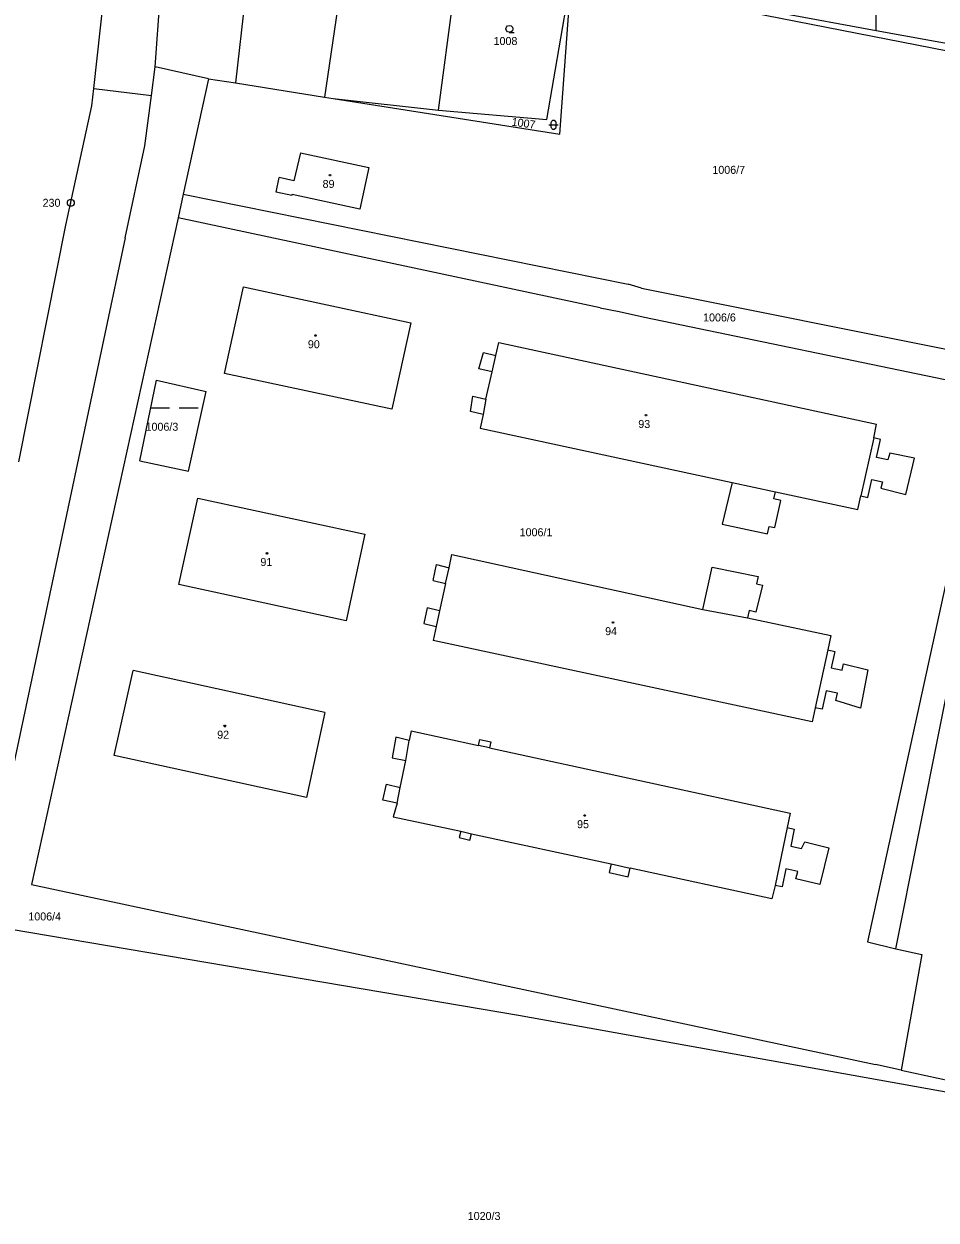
# Model space of a CAD drawing. Extents: x -850689 to -847910, y -1058374 to -1054747.
# Drawn here: x -849600.1 to -849406.4, y -1056698.2 to -1056444.2 of the extents above; entities that cross this region are included whole.
import ezdxf

# ---------------------------------------------------------------- set-up
doc = ezdxf.new("R2010")
doc.units = 0
for name, color, linetype in [('KN_HRANICE', 7, 'Continuous'), ('KN_KULTURY', 7, 'Continuous'), ('KN_MEZNIKY', 7, 'Continuous'), ('KN_PARCELY', 7, 'Continuous'), ('KN_SLUCKY', 7, 'Continuous'), ('KN_STAVEBNI', 7, 'Continuous')]:
    doc.layers.add(name, color=color, linetype=linetype)

# ---------------------------------------------------------------- blocks, each defined once
blk = doc.blocks.new('101')
blk.add_line((-0.05, 0), (0.05, 0))
blk.add_lwpolyline([(0.19, 0.72), (0.53, 0.53), (0.72, 0.19), (0.72, -0.2), (0.53, -0.54), (0.19, -0.73), (-0.2, -0.73), (-0.54, -0.54), (-0.73, -0.2), (-0.73, 0.19), (-0.54, 0.53), (-0.2, 0.72), (0.19, 0.72)])
blk = doc.blocks.new('304')
blk.add_lwpolyline([(0, 0), (-0.38, 0.1), (-0.65, 0.37), (-0.75, 0.74), (-0.65, 1.11), (-0.38, 1.38), (-0.01, 1.48), (0.36, 1.38), (0.63, 1.11), (0.73, 0.73), (0.63, 0.35), (0.36, 0.08), (-0.02, -0.02), (0.98, -0.02)])
blk = doc.blocks.new('316')
for points in [[(-1, 1), (0.27, 1), (1, 1)], [(-0.5, 1.5), (-0.4, 1.79), (-0.15, 1.97), (0.16, 1.97), (0.41, 1.79), (0.51, 1.5), (0.51, 0.5), (0.41, 0.21), (0.16, 0.03), (-0.15, 0.03), (-0.4, 0.21), (-0.5, 0.5), (-0.5, 1.5)]]:
    blk.add_lwpolyline(points)
blk = doc.blocks.new('803')
for p, q in [((-7.5, 0), (-1.5, 0)), ((1.5, 0), (7.5, 0))]:
    blk.add_line(p, q)
blk = doc.blocks.new('402')
blk.add_lwpolyline([(0.09, 0.15), (0.18, 0), (0.09, -0.15), (-0.09, -0.15), (-0.18, 0), (-0.09, 0.15), (0.09, 0.15)])

msp = doc.modelspace()

# ---------------------------------------------------------------- linework, layer by layer
at = {"layer": 'KN_HRANICE'}
for p, q in [((-849585.31, -1056457.89), (-849579.89, -1056409.19)), ((-849419.09, -1056445.59), (-849419.34, -1056413.3)), ((-849572.24, -1056453.32), (-849570.06, -1056422.29)), ((-849551.37, -1056423.56), (-849555.21, -1056456.71)), ((-849531.06, -1056424.37), (-849536.26, -1056459.7)), ((-849512.05, -1056462.5), (-849507.03, -1056425.02)), ((-849489.06, -1056464.49), (-849483.86, -1056434.18)), ((-849486.28, -1056467.61), (-849483.86, -1056434.18)), ((-849371.72, -1056456.31), (-849483.86, -1056434.18)), ((-849439.82, -1056441.73), (-849419.09, -1056445.59)), ((-849419.09, -1056445.59), (-849397.43, -1056449.45)), ((-849573.04, -1056459.35), (-849572.24, -1056453.32)), ((-849560.89, -1056455.81), (-849572.24, -1056453.32)), ((-849560.89, -1056455.81), (-849566.27, -1056480.31)), ((-849560.89, -1056455.81), (-849555.21, -1056456.71)), ((-849555.21, -1056456.71), (-849536.26, -1056459.7)), ((-849585.72, -1056461.57), (-849585.31, -1056457.89)), ((-849585.31, -1056457.89), (-849573.04, -1056459.35)), ((-849574.46, -1056470.04), (-849573.04, -1056459.35)), ((-849536.26, -1056459.7), (-849534.42, -1056460.02)), ((-849534.42, -1056460.02), (-849512.05, -1056462.5)), ((-849534.42, -1056460.02), (-849486.28, -1056467.61)), ((-849591.21, -1056486.93), (-849585.72, -1056461.57)), ((-849512.05, -1056462.5), (-849489.06, -1056464.49)), ((-849578.61, -1056489.59), (-849574.46, -1056470.04)), ((-849541.4, -1056471.57), (-849542.79, -1056477.49)), ((-849541.4, -1056471.57), (-849526.88, -1056474.69)), ((-849526.88, -1056474.69), (-849528.79, -1056483.54)), ((-849546.56, -1056479.92), (-849545.91, -1056476.77)), ((-849542.79, -1056477.49), (-849545.91, -1056476.77)), ((-849566.27, -1056480.31), (-849567.38, -1056485.36)), ((-849566.27, -1056480.31), (-849471.74, -1056499.48)), ((-849543.23, -1056480.62), (-849546.56, -1056479.92)), ((-849543.17, -1056480.41), (-849543.23, -1056480.62)), ((-849528.79, -1056483.54), (-849543.17, -1056480.41)), ((-849567.38, -1056485.36), (-849598.49, -1056626.95)), ((-849477.73, -1056504.47), (-849567.38, -1056485.36)), ((-849601.24, -1056537.2), (-849591.21, -1056486.93)), ((-849578.61, -1056489.59), (-849604.54, -1056611.95)), ((-849557.51, -1056518.41), (-849553.5, -1056500.01)), ((-849553.5, -1056500.01), (-849517.96, -1056507.67)), ((-849468.95, -1056500.27), (-849471.74, -1056499.48)), ((-849468.95, -1056500.27), (-849395.37, -1056515.06)), ((-849477.73, -1056504.47), (-849473.68, -1056505.23)), ((-849473.68, -1056505.23), (-849468.29, -1056506.44)), ((-849517.96, -1056507.67), (-849521.94, -1056526.03)), ((-849468.29, -1056506.44), (-849396.69, -1056521.32)), ((-849499.88, -1056514.57), (-849499.27, -1056511.85)), ((-849499.27, -1056511.85), (-849418.99, -1056529.19)), ((-849503.48, -1056517.45), (-849502.53, -1056513.94)), ((-849502.53, -1056513.94), (-849499.88, -1056514.57)), ((-849521.94, -1056526.03), (-849557.51, -1056518.41)), ((-849500.67, -1056518.05), (-849503.48, -1056517.45)), ((-849502.01, -1056523.87), (-849500.67, -1056518.05)), ((-849575.54, -1056536.95), (-849571.99, -1056519.87)), ((-849571.99, -1056519.87), (-849561.38, -1056522.23)), ((-849565.16, -1056539.17), (-849561.38, -1056522.23)), ((-849505.28, -1056526.5), (-849504.75, -1056523.24)), ((-849504.75, -1056523.24), (-849502.01, -1056523.87)), ((-849395.95, -1056524.56), (-849420.9, -1056639.14)), ((-849502.59, -1056527.12), (-849505.28, -1056526.5)), ((-849502.59, -1056527.12), (-849503.23, -1056530.04)), ((-849503.23, -1056530.04), (-849449.7, -1056541.59)), ((-849419.61, -1056532.12), (-849418.99, -1056529.19)), ((-849418.17, -1056532.44), (-849419.61, -1056532.12)), ((-849419.01, -1056536.24), (-849418.17, -1056532.44)), ((-849416.58, -1056536.78), (-849419.01, -1056536.24)), ((-849416.2, -1056535.32), (-849416.58, -1056536.78)), ((-849410.97, -1056536.39), (-849416.2, -1056535.32)), ((-849575.54, -1056536.95), (-849565.16, -1056539.17)), ((-849412.78, -1056544.11), (-849410.97, -1056536.39)), ((-849420.87, -1056544.76), (-849420.03, -1056540.95)), ((-849420.03, -1056540.95), (-849417.76, -1056541.44)), ((-849417.76, -1056541.44), (-849418.09, -1056542.81)), ((-849449.7, -1056541.59), (-849451.79, -1056550.43)), ((-849440.8, -1056545.08), (-849440.47, -1056543.57)), ((-849440.47, -1056543.57), (-849422.97, -1056547.32)), ((-849418.09, -1056542.81), (-849412.78, -1056544.11)), ((-849567.23, -1056563.28), (-849563.21, -1056544.94)), ((-849563.21, -1056544.94), (-849527.69, -1056552.58)), ((-849439.33, -1056545.4), (-849440.8, -1056545.08)), ((-849440.61, -1056551.14), (-849439.33, -1056545.4)), ((-849422.97, -1056547.32), (-849422.33, -1056544.44)), ((-849422.33, -1056544.44), (-849420.87, -1056544.76)), ((-849451.79, -1056550.43), (-849442.14, -1056552.5)), ((-849442.14, -1056552.5), (-849441.84, -1056550.93)), ((-849441.84, -1056550.93), (-849440.61, -1056551.14)), ((-849527.69, -1056552.58), (-849531.67, -1056570.96)), ((-849513.19, -1056562.36), (-849512.47, -1056559.02)), ((-849512.47, -1056559.02), (-849509.82, -1056559.67)), ((-849509.82, -1056559.67), (-849509.21, -1056556.86)), ((-849509.21, -1056556.86), (-849455.93, -1056568.52)), ((-849414.91, -1056640.62), (-849398.6, -1056558.62)), ((-849455.93, -1056568.52), (-849453.9, -1056559.55)), ((-849453.9, -1056559.55), (-849444.14, -1056561.56)), ((-849444.14, -1056561.56), (-849444.51, -1056563.11)), ((-849531.67, -1056570.96), (-849567.23, -1056563.28)), ((-849513.19, -1056562.36), (-849510.55, -1056563)), ((-849510.55, -1056563), (-849511.82, -1056568.87)), ((-849443.23, -1056563.42), (-849444.62, -1056569.13)), ((-849444.51, -1056563.11), (-849443.23, -1056563.42)), ((-849514.46, -1056568.21), (-849515.18, -1056571.52)), ((-849511.82, -1056568.87), (-849514.46, -1056568.21)), ((-849446.08, -1056568.77), (-849446.45, -1056570.29)), ((-849444.62, -1056569.13), (-849446.08, -1056568.77)), ((-849515.18, -1056571.52), (-849512.54, -1056572.2)), ((-849446.45, -1056570.29), (-849428.7, -1056574.09)), ((-849512.54, -1056572.2), (-849513.19, -1056575.16)), ((-849428.7, -1056574.09), (-849429.35, -1056577.14)), ((-849432.67, -1056592.43), (-849513.19, -1056575.16)), ((-849429.35, -1056577.14), (-849427.87, -1056577.46)), ((-849427.87, -1056577.46), (-849428.63, -1056580.98)), ((-849580.99, -1056599.58), (-849576.93, -1056581.48)), ((-849536.18, -1056590.43), (-849576.93, -1056581.48)), ((-849428.63, -1056580.98), (-849426.33, -1056581.47)), ((-849426.33, -1056581.47), (-849426.02, -1056580.11)), ((-849426.02, -1056580.11), (-849420.83, -1056581.39)), ((-849420.83, -1056581.39), (-849422.43, -1056589.48)), ((-849429.71, -1056585.84), (-849430.55, -1056589.74)), ((-849427.32, -1056586.35), (-849429.71, -1056585.84)), ((-849427.67, -1056587.9), (-849427.32, -1056586.35)), ((-849432.02, -1056589.41), (-849432.67, -1056592.43)), ((-849430.55, -1056589.74), (-849432.02, -1056589.41)), ((-849422.43, -1056589.48), (-849427.67, -1056587.9)), ((-849536.18, -1056590.43), (-849540.11, -1056608.51)), ((-849517.9, -1056594.35), (-849518.32, -1056596.36)), ((-849517.9, -1056594.35), (-849503.57, -1056597.45)), ((-849521.13, -1056595.68), (-849521.91, -1056600.04)), ((-849518.32, -1056596.36), (-849521.13, -1056595.68)), ((-849503.57, -1056597.45), (-849503.29, -1056596.18)), ((-849503.29, -1056596.18), (-849500.96, -1056596.67)), ((-849500.96, -1056596.67), (-849501.24, -1056597.95)), ((-849540.11, -1056608.51), (-849580.99, -1056599.58)), ((-849501.24, -1056597.95), (-849437.33, -1056611.82)), ((-849521.91, -1056600.04), (-849518.99, -1056600.65)), ((-849520.21, -1056606.34), (-849518.99, -1056600.65)), ((-849523.86, -1056609.02), (-849523.12, -1056605.65)), ((-849523.12, -1056605.65), (-849520.21, -1056606.34)), ((-849520.85, -1056609.71), (-849523.86, -1056609.02)), ((-849520.85, -1056609.71), (-849521.67, -1056612.57)), ((-849521.67, -1056612.57), (-849507.35, -1056615.67)), ((-849437.33, -1056611.82), (-849437.98, -1056614.87)), ((-849437.98, -1056614.87), (-849436.49, -1056615.19)), ((-849507.35, -1056615.67), (-849507.67, -1056617.01)), ((-849507.67, -1056617.01), (-849505.39, -1056617.56)), ((-849505.39, -1056617.56), (-849505.05, -1056616.17)), ((-849505.05, -1056616.17), (-849475.39, -1056622.6)), ((-849436.49, -1056615.19), (-849437.24, -1056618.81)), ((-849437.24, -1056618.81), (-849434.95, -1056619.29)), ((-849434.95, -1056619.29), (-849434.25, -1056617.87)), ((-849434.25, -1056617.87), (-849429.16, -1056619.16)), ((-849429.16, -1056619.16), (-849431.06, -1056626.98)), ((-849475.39, -1056622.6), (-849475.79, -1056624.45)), ((-849475.79, -1056624.45), (-849471.77, -1056625.33)), ((-849471.77, -1056625.33), (-849471.36, -1056623.48)), ((-849441.28, -1056630), (-849471.36, -1056623.48)), ((-849438.28, -1056623.66), (-849439.09, -1056627.48)), ((-849435.76, -1056624.18), (-849438.28, -1056623.66)), ((-849436.15, -1056625.79), (-849435.76, -1056624.18)), ((-849598.49, -1056626.95), (-849419.22, -1056665.19)), ((-849440.56, -1056627.16), (-849441.28, -1056630)), ((-849439.09, -1056627.48), (-849440.56, -1056627.16)), ((-849431.06, -1056626.98), (-849436.15, -1056625.79)), ((-849602.81, -1056636.44), (-849495.08, -1056654.69)), ((-849420.9, -1056639.14), (-849414.91, -1056640.62)), ((-849414.91, -1056640.62), (-849409.39, -1056641.82)), ((-849409.39, -1056641.82), (-849413.8, -1056666.37)), ((-849495.08, -1056654.69), (-849386.31, -1056674.19)), ((-849413.8, -1056666.37), (-849419.22, -1056665.19)), ((-849413.8, -1056666.37), (-849386.24, -1056672.33))]:
    msp.add_line(p, q, dxfattribs=at)
at = {"layer": 'KN_SLUCKY'}
for p, q in [((-849500.67, -1056518.05), (-849499.88, -1056514.57)), ((-849502.01, -1056523.87), (-849502.59, -1056527.12)), ((-849419.61, -1056532.12), (-849422.33, -1056544.44)), ((-849449.7, -1056541.59), (-849440.47, -1056543.57)), ((-849510.55, -1056563), (-849509.82, -1056559.67)), ((-849511.82, -1056568.87), (-849512.54, -1056572.2)), ((-849455.93, -1056568.52), (-849446.45, -1056570.29)), ((-849429.35, -1056577.14), (-849432.02, -1056589.41)), ((-849518.99, -1056600.65), (-849518.32, -1056596.36)), ((-849501.24, -1056597.95), (-849503.57, -1056597.45)), ((-849520.85, -1056609.71), (-849520.21, -1056606.34)), ((-849437.98, -1056614.87), (-849440.56, -1056627.16)), ((-849507.35, -1056615.67), (-849505.05, -1056616.17)), ((-849475.39, -1056622.6), (-849471.36, -1056623.48))]:
    msp.add_line(p, q, dxfattribs=at)
at = {"layer": 'KN_STAVEBNI'}
for p, q in [((-849541.4, -1056471.57), (-849542.79, -1056477.49)), ((-849541.4, -1056471.57), (-849526.88, -1056474.69)), ((-849526.88, -1056474.69), (-849528.79, -1056483.54)), ((-849546.56, -1056479.92), (-849545.91, -1056476.77)), ((-849542.79, -1056477.49), (-849545.91, -1056476.77)), ((-849543.23, -1056480.62), (-849546.56, -1056479.92)), ((-849543.17, -1056480.41), (-849543.23, -1056480.62)), ((-849528.79, -1056483.54), (-849543.17, -1056480.41)), ((-849557.51, -1056518.41), (-849553.5, -1056500.01)), ((-849553.5, -1056500.01), (-849517.96, -1056507.67)), ((-849517.96, -1056507.67), (-849521.94, -1056526.03)), ((-849499.88, -1056514.57), (-849499.27, -1056511.85)), ((-849499.27, -1056511.85), (-849418.99, -1056529.19)), ((-849500.67, -1056518.05), (-849499.88, -1056514.57)), ((-849521.94, -1056526.03), (-849557.51, -1056518.41)), ((-849502.01, -1056523.87), (-849500.67, -1056518.05)), ((-849502.01, -1056523.87), (-849502.59, -1056527.12)), ((-849502.59, -1056527.12), (-849503.23, -1056530.04)), ((-849503.23, -1056530.04), (-849449.7, -1056541.59)), ((-849419.61, -1056532.12), (-849418.99, -1056529.19)), ((-849419.61, -1056532.12), (-849422.33, -1056544.44)), ((-849449.7, -1056541.59), (-849440.47, -1056543.57)), ((-849440.47, -1056543.57), (-849422.97, -1056547.32)), ((-849567.23, -1056563.28), (-849563.21, -1056544.94)), ((-849563.21, -1056544.94), (-849527.69, -1056552.58)), ((-849422.97, -1056547.32), (-849422.33, -1056544.44)), ((-849527.69, -1056552.58), (-849531.67, -1056570.96)), ((-849509.82, -1056559.67), (-849509.21, -1056556.86)), ((-849509.21, -1056556.86), (-849455.93, -1056568.52)), ((-849510.55, -1056563), (-849509.82, -1056559.67)), ((-849531.67, -1056570.96), (-849567.23, -1056563.28)), ((-849510.55, -1056563), (-849511.82, -1056568.87)), ((-849511.82, -1056568.87), (-849512.54, -1056572.2)), ((-849455.93, -1056568.52), (-849446.45, -1056570.29)), ((-849446.45, -1056570.29), (-849428.7, -1056574.09)), ((-849512.54, -1056572.2), (-849513.19, -1056575.16)), ((-849428.7, -1056574.09), (-849429.35, -1056577.14)), ((-849432.67, -1056592.43), (-849513.19, -1056575.16)), ((-849429.35, -1056577.14), (-849432.02, -1056589.41)), ((-849580.99, -1056599.58), (-849576.93, -1056581.48)), ((-849536.18, -1056590.43), (-849576.93, -1056581.48)), ((-849432.02, -1056589.41), (-849432.67, -1056592.43)), ((-849536.18, -1056590.43), (-849540.11, -1056608.51)), ((-849517.9, -1056594.35), (-849518.32, -1056596.36)), ((-849517.9, -1056594.35), (-849503.57, -1056597.45)), ((-849518.99, -1056600.65), (-849518.32, -1056596.36)), ((-849540.11, -1056608.51), (-849580.99, -1056599.58)), ((-849501.24, -1056597.95), (-849503.57, -1056597.45)), ((-849501.24, -1056597.95), (-849437.33, -1056611.82)), ((-849520.21, -1056606.34), (-849518.99, -1056600.65)), ((-849520.85, -1056609.71), (-849520.21, -1056606.34)), ((-849520.85, -1056609.71), (-849521.67, -1056612.57)), ((-849521.67, -1056612.57), (-849507.35, -1056615.67)), ((-849437.33, -1056611.82), (-849437.98, -1056614.87)), ((-849437.98, -1056614.87), (-849440.56, -1056627.16)), ((-849507.35, -1056615.67), (-849505.05, -1056616.17)), ((-849505.05, -1056616.17), (-849475.39, -1056622.6)), ((-849475.39, -1056622.6), (-849471.36, -1056623.48)), ((-849441.28, -1056630), (-849471.36, -1056623.48)), ((-849440.56, -1056627.16), (-849441.28, -1056630))]:
    msp.add_line(p, q, dxfattribs=at)

# ---------------------------------------------------------------- block references
at = {"layer": 'KN_KULTURY'}
for name, p in [('304', (-849497, -1056445.96)), ('316', (-849487.62, -1056466.61)), ('402', (-849535.1, -1056476.31)), ('402', (-849538.19, -1056510.36)), ('402', (-849468, -1056527.3)), ('402', (-849548.51, -1056556.62)), ('402', (-849475, -1056571.3)), ('402', (-849557.45, -1056593.3)), ('402', (-849481, -1056612.3))]:
    msp.add_blockref(name, p, dxfattribs=at)
at = {"layer": 'KN_KULTURY', "xscale": 0.67, "yscale": 0.67}
msp.add_blockref('803', (-849568.17, -1056525.73), dxfattribs=at)
at = {"layer": 'KN_MEZNIKY'}
msp.add_blockref('101', (-849590.17, -1056482.17), dxfattribs=at)

# ---------------------------------------------------------------- texts
msp.add_text('230', height=1.7, dxfattribs=at).set_placement((-849596.16, -1056483.02))
at = {"layer": 'KN_PARCELY'}
for s, p in [('1008', (-849500.36, -1056448.66)), ('1006/7', (-849453.88, -1056476.02)), ('89', (-849536.68, -1056479.01)), ('1006/6', (-849455.85, -1056507.37)), ('90', (-849539.81, -1056513.06)), ('93', (-849469.62, -1056530)), ('1006/3', (-849574.29, -1056530.59)), ('1006/1', (-849494.82, -1056553)), ('91', (-849549.89, -1056559.32)), ('94', (-849476.66, -1056574)), ('92', (-849559.07, -1056596)), ('95', (-849482.62, -1056615)), ('1006/4', (-849599.19, -1056634.6)), ('1020/3', (-849505.85, -1056698.22))]:
    msp.add_text(s, height=1.7, dxfattribs=at).set_placement(p)
msp.add_text('1007', height=1.7, rotation=352.426, dxfattribs=at).set_placement((-849496.6, -1056465.77))

doc.saveas('drawing.dxf')
